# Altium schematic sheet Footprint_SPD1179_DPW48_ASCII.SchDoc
size A4; 项目编号: SPSZ2023-052501A; 项目名称: 三相PFC-2.2KW压机+700W风机
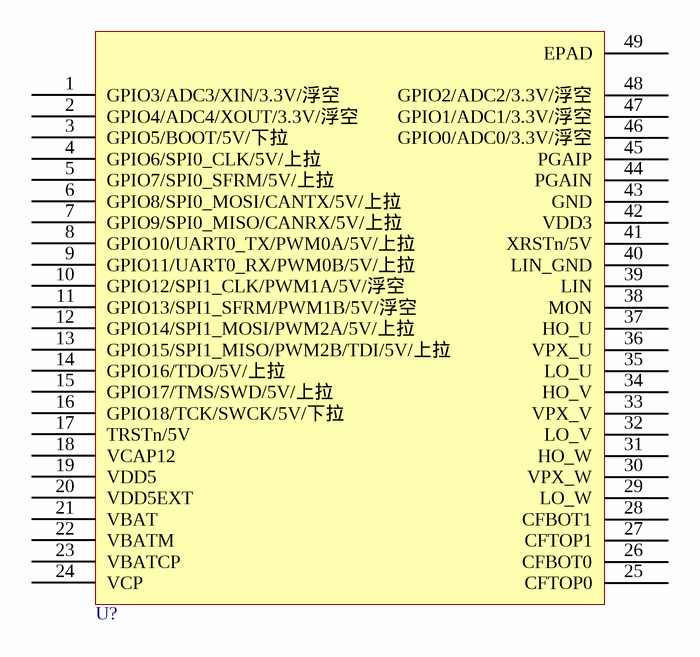
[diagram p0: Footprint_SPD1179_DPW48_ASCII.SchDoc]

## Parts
U?  SPD1179  [QFN48-0.5-1179-QFN50P700X700X90_HS-49M]  (value not drawn)

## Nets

Not connected (* = marked no-connect by the designer): U? 1(GPIO3/ADC3/XIN/3.3V/浮空) 2(GPIO4/ADC4/XOUT/3.3V/浮空) 3(GPIO5/BOOT/5V/下拉) 4(GPIO6/SPI0_CLK/5V/上拉) 5(GPIO7/SPI0_SFRM/5V/上拉) 6(GPIO8/SPI0_MOSI/CANTX/5V/上拉) 7(GPIO9/SPI0_MISO/CANRX/5V/上拉) 8(GPIO10/UART0_TX/PWM0A/5V/上拉) 9(GPIO11/UART0_RX/PWM0B/5V/上拉) 10(GPIO12/SPI1_CLK/PWM1A/5V/浮空) 11(GPIO13/SPI1_SFRM/PWM1B/5V/浮空) 12(GPIO14/SPI1_MOSI/PWM2A/5V/上拉) 13(GPIO15/SPI1_MISO/PWM2B/TDI/5V/上拉) 14(GPIO16/TDO/5V/上拉) 15(GPIO17/TMS/SWD/5V/上拉) 16(GPIO18/TCK/SWCK/5V/下拉) 17(TRSTn/5V) 18(VCAP12) 19(VDD5) 20(VDD5EXT) 21(VBAT) 22(VBATM) 23(VBATCP) 24(VCP) 25(CFTOP0) 26(CFBOT0) 27(CFTOP1) 28(CFBOT1) 29(LO_W) 30(VPX_W) 31(HO_W) 32(LO_V) 33(VPX_V) 34(HO_V) 35(LO_U) 36(VPX_U) 37(HO_U) 38(MON) 39(LIN) 40(LIN_GND) 41(XRSTn/5V) 42(VDD3) 43(GND) 44(PGAIN) 45(PGAIP) 46(GPIO0/ADC0/3.3V/浮空) 47(GPIO1/ADC1/3.3V/浮空) 48(GPIO2/ADC2/3.3V/浮空) 49(EPAD)

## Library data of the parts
U? = U_SPD1179: 32-bit ARM CM4 automotives MCU with HV power management, LIN and PDRV; Manufacture: Spintrol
